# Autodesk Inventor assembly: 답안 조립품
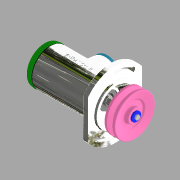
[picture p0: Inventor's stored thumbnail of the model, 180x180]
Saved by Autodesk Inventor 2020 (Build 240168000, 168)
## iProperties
Created: 2022-05
Part Number: 답안 조립품
Document SubType Name: Assembly
Designer: Student
Author: Student
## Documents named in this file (22)
- C:\Users\Student\Desktop\720506V1027\답안 조립품.iam
- C:\Users\Student\Desktop\720506V1027\본체.ipt
- C:\Users\Student\Desktop\720506V1027\베어링 6202.ipt
- C:\Users\Student\Desktop\720506V1027\오일 실 15 x 30 x 7.ipt
- C:\Users\Student\Desktop\720506V1027\사이드 커버.ipt
- 사이드 커버.ipt
- C:\Users\Student\Desktop\720506V1027\멈춤링 35 x 1.6.ipt
- C:\Users\Student\Desktop\720506V1027\축.ipt
- C:\Users\Student\Desktop\720506V1027\부시1.ipt
- C:\Users\Student\Desktop\720506V1027\멈춤링 15 x 1.ipt
- C:\Users\Student\Desktop\720506V1027\부시2.ipt
- C:\Users\Student\Desktop\720506V1027\와셔 10 x 21.ipt
- C:\Users\Student\Desktop\720506V1027\너트 M10.ipt
- C:\Users\Student\Desktop\720506V1027\V-벨트풀리.ipt
- C:\Users\Student\Desktop\720506V1027\키 4 x 4.ipt
- C:\Users\Student\Desktop\720506V1027\와셔 4 x 16.ipt
- C:\Users\Student\Desktop\720506V1027\볼트 M4 x 10.ipt
- C:\Users\Student\Desktop\720506V1027\멈춤나사 M3.ipt
- C:\Users\Student\Desktop\720506V1027\탑 커버.ipt
- C:\Users\Student\Desktop\720506V1027\와셔 3 x 6.ipt
- C:\Users\Student\Desktop\720506V1027\십자볼트 M3 x 10.ipt
- C:\Users\Student\Desktop\720506V1027\개스킷.ipt
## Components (3 placed, 3 different names)
1. V-벨트풀리:1
2. ISO 4017 M4 x 10:1
3. 개스킷:1
